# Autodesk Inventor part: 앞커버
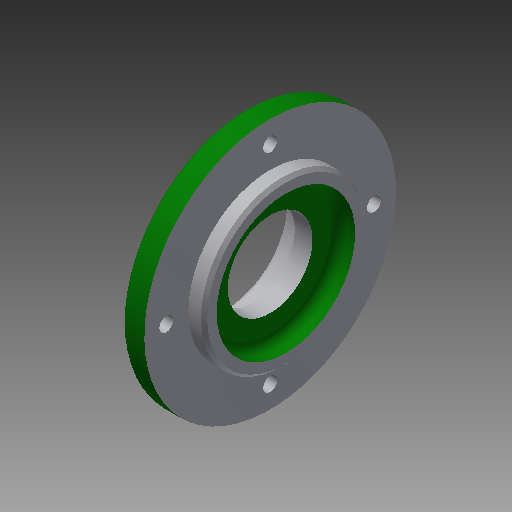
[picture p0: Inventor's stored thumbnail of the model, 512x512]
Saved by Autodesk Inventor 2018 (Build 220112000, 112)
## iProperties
Created: 2019-01
Part Number: 앞커버
Material: 알루미늄 6061
Document SubType Name: Modeling
Designer: mduedu
Density: 1 g/cm^3
Appearance: 알루미늄 - 평지
Author: mduedu
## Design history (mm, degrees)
sketch "스케치1"
  geometry: L1 (0, 0)-(6, 0); L2 (6, 0)-(6, 25); L3 (6, 25)-(0, 25); L4 (0, 25)-(0, 0); L5 (6, 0)-(14, 0); L6 (14, 0)-(14, 40); L7 (14, 40)-(6, 40); L8 (6, 40)-(6, 0); L9 (14, 0)-(19, 0); L10 (19, 0)-(19, 26); L11 (19, 26)-(14, 26); L12 (14, 26)-(14, 0)
  constraints: 24 end point, 6 parallel, 3 horizontal, 3 perpendicular
  dimensions: "d6" = 80 diameter of L7 L5; "d8" = 50 diameter of L3 L1; "d9" = 52 diameter of L11 L9; "d10" = 5 distance of L10.end L11.end; "d11" = 6 distance of L2.end L3.end; "d12" = 19 distance between parallel lines of L4 L10; "d13" = 8 distance of L6.end L7.end (derived)
revolve "회전1" sketch "스케치1" stored, may be unused: angle "d5" = 90 deg
sketch "스케치2"
  geometry: C1 r 13.5 at (0, 0); 1 further point
  constraints: 1 centre point, 1 coincident
  dimensions: "d14" = 27 diameter of C1
extrude "돌출1" cut sketch "스케치2" extent not by distance; stored distance "d15" = 10; taper "d16" = 0 deg
sketch "스케치3" dims "d17" = 66
  geometry: 6 further points
  constraints: 2 vertical alignment, 1 coincident, 7 other
  dimensions: "d20" = 360 deg dimension on point (0, 0) point (0, 33) (derived)
sketch "스케치4"
  geometry: 4 further points
  constraints: 4 other
hole "구멍1" sketch "스케치4" at (-33, 0), (0, -33), (33, 0), (0, 33) diameter "d22" = 4.5; stored, may be unused: countersink angle "d26" = 90 deg, drill point angle "d28" = 0 deg; dims "d23" = 6, "d24" = 8, "d25" = 4.6, "d27" = 8
fillet "모깎기1" dims "d29" = 3
sketch "스케치5"
  geometry: C1 r 19 at (0, 0); 1 further point
  constraints: 1 centre point, 1 coincident
  dimensions: "d30" = 38 diameter of C1
extrude "돌출2" cut sketch "스케치5" distance "d31" = 8.3; taper "d32" = 0 deg
fillet "모깎기2" dims "d33" = 3
chamfer "모따기1" distance "d34" = 0.8; stored, may be unused: second distance "d35" = 2, angle "d36" = 30 deg
fillet "모깎기3" dims "d37" = 0.5
sketch "스케치6"
  geometry: C1 r 22 at (0, 0); 1 further point
  constraints: 1 centre point, 1 coincident
  dimensions: "d38" = 44 diameter of C1
extrude "돌출3" cut sketch "스케치6" distance "d39" = 5; taper "d40" = 0 deg
fillet "모깎기4" dims "d41" = 3
chamfer "모따기2" distance "d42" = 1; stored, may be unused: second distance "d43" = 2, angle "d44" = 30 deg
node "솔리드1"
